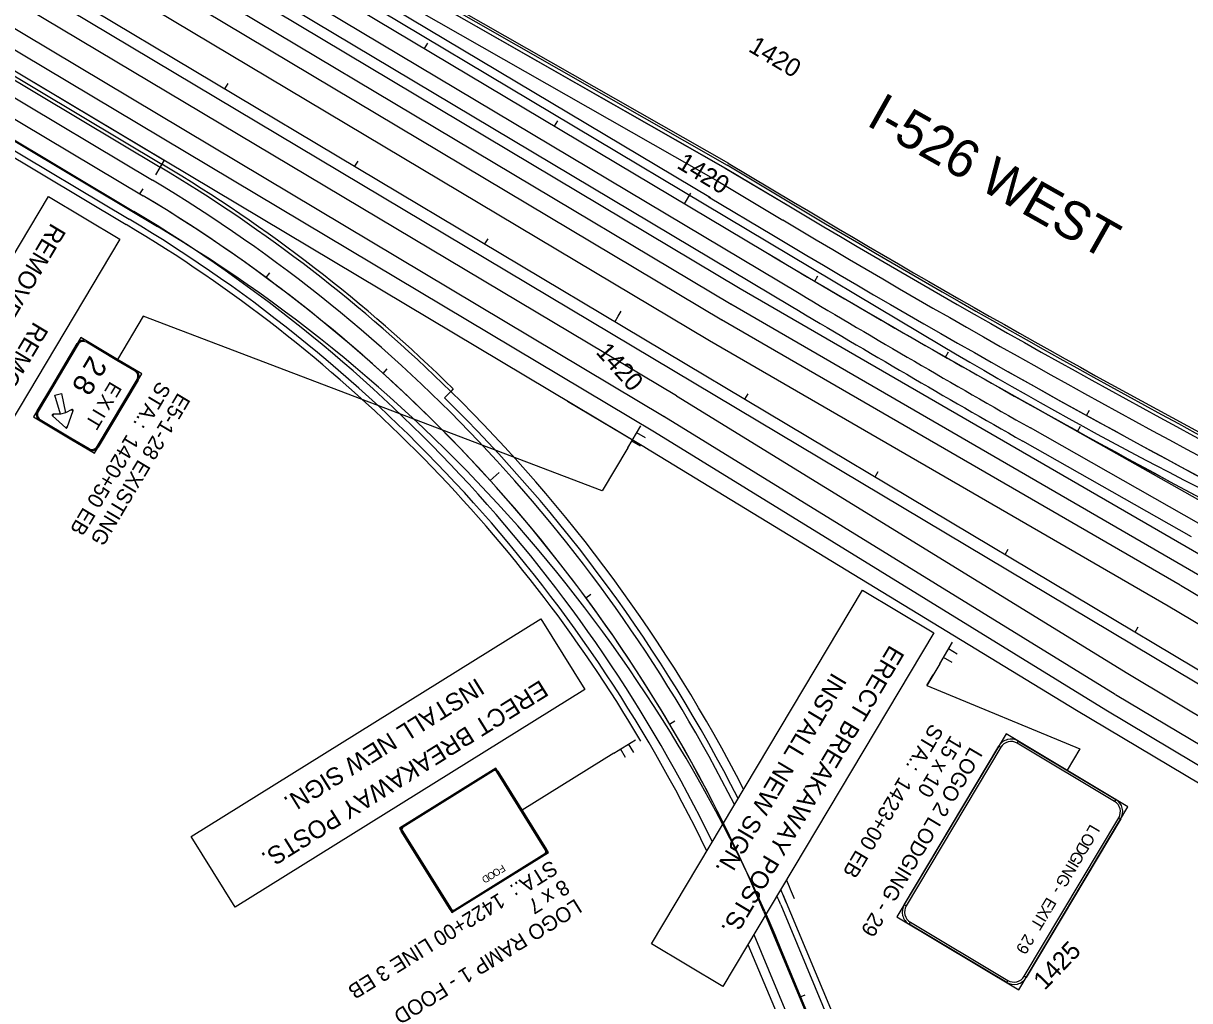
# Model space of a CAD drawing. Extents: x 2338610 to 2351914, y 366540 to 376484.
# Drawn here: x 2347857 to 2348627, y 368264 to 368909 of the extents above; entities that cross this region are included whole.
import ezdxf

# ---------------------------------------------------------------- set-up
doc = ezdxf.new("R2010")
doc.units = 0
for name, color, linetype in [('RD_HC_Cl', 7, 'Continuous'), ('RD_HC_CL_Rel', 7, 'Continuous'), ('RD_PD_Final_LnLine', 7, 'Continuous'), ('RD_PD_Final_TrvlWay', 7, 'Continuous'), ('RD_PD_GR', 7, 'Continuous'), ('RD_PD_MedBWall', 7, 'Continuous'), ('RD_PD_MedGR', 7, 'Continuous'), ('RD_PD_NOISE-WALL-GM', 7, 'Continuous'), ('RD_PD_PaveShd', 7, 'Continuous'), ('TR PM UNASSIGNED 3', 7, 'Continuous'), ('TR SN EXISTING - BREAK-AWAY SIGN SUPPORTS', 7, 'Continuous'), ('TR SN EXTRUDED PANEL SIGNS - GROUND MOUNTED', 7, 'Continuous'), ('TR SN EXTRUDED PANEL SIGNS- MOUNTED OVERHEAD', 7, 'Continuous'), ('TR SN UNASSIGNED 4', 7, 'Continuous'), ('TR SN UNASSIGNED 7', 7, 'Continuous')]:
    doc.layers.add(name, color=color, linetype=linetype)

msp = doc.modelspace()

# ---------------------------------------------------------------- linework, layer by layer
at = {"layer": 'RD_HC_Cl'}
for p, q in [((2346281.57, 369885.43), (2351112.4, 367003.22)), ((2346606.48, 369804.53), (2348463.13, 368696.8)), ((2346606.48, 369804.53), (2348463.13, 368696.8)), ((2346606.48, 369804.53), (2348463.13, 368696.8)), ((2346606.48, 369804.53), (2348463.13, 368696.8))]:
    msp.add_line(p, q, dxfattribs=at)
msp.add_arc((2349948.99, 371187.23), 2900, 239.17851, 245.9774, dxfattribs=at)
msp.add_arc((2349948.99, 371187.23), 2900, 239.17851, 245.9774, dxfattribs=at)
msp.add_arc((2349948.99, 371187.23), 2900, 239.17851, 245.9774, dxfattribs=at)
msp.add_arc((2349948.99, 371187.23), 2900, 239.17851, 245.9774, dxfattribs=at)
at = {"layer": 'RD_HC_CL_Rel'}
for p, q in [((2346236.27, 369809.5), (2347935.64, 368795.61)), ((2347900.51, 369024.72), (2348345.88, 368759)), ((2348500.93, 368669.16), (2349129.79, 368315.43)), ((2348345.74, 368322.92), (2348612.9, 367684.58))]:
    msp.add_line(p, q, dxfattribs=at)
for centre, radius, start, end in [((2347423.27, 367936.84), 1000, 22.71075, 59.17851), ((2351938.58, 374780.68), 7012, 239.178507, 240.642806), ((2351938.58, 374780.68), 7000, 240.642806, 245.882475), ((2348774.65, 368059.29), 214.01, 62.97341, 174.06692)]:
    msp.add_arc(centre, radius, start, end, dxfattribs=at)
at = {"layer": 'RD_PD_Final_LnLine'}
for p, q in [((2346262.53, 369853.51), (2348279.79, 368649.96)), ((2346236.27, 369809.5), (2347935.64, 368795.61)), ((2346236.75, 369794.56), (2347945.19, 368775.26)), ((2346236.75, 369794.56), (2347945.19, 368775.26)), ((2346236.75, 369794.56), (2347945.19, 368775.26)), ((2346236.75, 369794.56), (2347945.19, 368775.26)), ((2346978.67, 369512.8), (2348317.92, 368713.76)), ((2348310.4, 368794.14), (2347906.4, 369035.17)), ((2347900.51, 369024.72), (2348345.88, 368759)), ((2348309.13, 368794.89), (2348352.02, 368769.3)), ((2348317.78, 368713.85), (2348620.78, 368538.7)), ((2348279.7, 368650.01), (2348577.74, 368466.56)), ((2348620.92, 368538.62), (2349820.78, 367822.75)), ((2348577.88, 368466.48), (2349209.46, 368089.66)), ((2348346.67, 368320.69), (2348585.38, 367750.35)), ((2348611.02, 367683.86), (2348357, 368298.46)), ((2348611.02, 367683.86), (2348357, 368298.46)), ((2348611.02, 367683.86), (2348357, 368298.46)), ((2348611.02, 367683.86), (2348357, 368298.46))]:
    msp.add_line(p, q, dxfattribs=at)
for centre, radius, start, end in [((2347423.27, 367936.84), 1000, 26.39949, 59.17851), ((2347432.83, 367916.49), 1000, 22.45591, 59.17851), ((2347432.83, 367916.49), 1000, 22.45591, 59.17851), ((2347432.83, 367916.49), 1000, 22.45591, 59.17851), ((2347432.83, 367916.49), 1000, 22.45591, 59.17851), ((2351938.58, 374780.68), 7000, 239.178507, 245.882475), ((2351938.58, 374780.68), 7012, 239.178507, 242.089491), ((2351938.58, 374780.68), 7012, 240.642806, 243.703137)]:
    msp.add_arc(centre, radius, start, end, dxfattribs=at)
at = {"layer": 'RD_PD_Final_TrvlWay'}
for p, q in [((2346256.38, 369843.21), (2348273.55, 368639.71)), ((2346242.42, 369819.8), (2347941.79, 368805.92)), ((2346217.64, 369806.64), (2347929.49, 368785.3)), ((2346984.82, 369523.11), (2348324.07, 368724.07)), ((2347907.65, 369037.48), (2348315.23, 368805.23)), ((2347894.36, 369014.41), (2348368.91, 368731.28)), ((2348315.23, 368805.23), (2348358.17, 368779.61)), ((2348323.79, 368724.24), (2348626.93, 368549.01)), ((2349153.03, 368283.92), (2348521.76, 368642.31)), ((2348273.55, 368639.71), (2348571.59, 368456.26)), ((2348626.93, 368549.01), (2349813.16, 367841.27)), ((2348571.59, 368456.26), (2349076.83, 368154.82)), ((2348356.81, 368327.55), (2348396.32, 368233.15)), ((2348339.03, 368307.87), (2348438.16, 368071.02))]:
    msp.add_line(p, q, dxfattribs=at)
for centre, radius, start, end in [((2347423.27, 367936.84), 1012, 26.83591, 59.17851), ((2347423.27, 367936.84), 988, 25.95023, 59.17851), ((2351938.58, 374780.68), 6988, 239.178507, 245.882475), ((2352567.57, 375768.6), 8194.67, 239.178507, 240.415096), ((2347423.27, 367936.84), 1012, 22.71075, 23.075), ((2348774.64, 368059.31), 230, 61.0108, 285.1623), ((2348774.64, 368059.31), 214, 61.0108, 285.16043)]:
    msp.add_arc(centre, radius, start, end, dxfattribs=at)
at = {"layer": 'RD_PD_GR'}
msp.add_line((2347001.09, 369327.57), (2347924.37, 368776.72), dxfattribs=at)
for centre, radius, start, end in [((2347423.27, 367936.84), 978, 30.66777, 59.17851), ((2347423.27, 367936.84), 1022, 27.19021, 45.55608), ((2347423.27, 367936.84), 1022, 22.71075, 23.48282), ((2348774.64, 368059.31), 240, 81.15571, 162.94062)]:
    msp.add_arc(centre, radius, start, end, dxfattribs=at)
at = {"layer": 'RD_PD_MedBWall'}
for p, q in [((2346754.62, 369528.57), (2347948.1, 368816.51)), ((2346753.42, 369526.57), (2347946.91, 368814.5)), ((2347912.6, 369046.17), (2348320.37, 368813.81)), ((2347913.76, 369048.19), (2348321.53, 368815.83)), ((2347946.91, 368814.5), (2347948.1, 368816.51)), ((2348320.17, 368813.93), (2348363.3, 368788.2)), ((2348321.37, 368815.93), (2348364.49, 368790.2)), ((2348140.52, 368668.15), (2348138.89, 368666.49))]:
    msp.add_line(p, q, dxfattribs=at)
for centre, radius, start, end in [((2347423.27, 367936.84), 1022, 45.55608, 59.17851), ((2347423.27, 367936.84), 1024.33, 45.55608, 59.17851), ((2351938.58, 374780.68), 6978, 239.178507, 245.882475), ((2351938.58, 374780.68), 6975.67, 239.178507, 245.882475)]:
    msp.add_arc(centre, radius, start, end, dxfattribs=at)
at = {"layer": 'RD_PD_MedGR'}
msp.add_line((2347144.89, 369361.04), (2349123.23, 368180.7), dxfattribs=at)
at = {"layer": 'RD_PD_NOISE-WALL-GM'}
for p, q in [((2347913.76, 369048.19), (2348321.53, 368815.83)), ((2347914.5, 369049.5), (2348322.27, 368817.14)), ((2348322.13, 368817.22), (2348365.26, 368791.49))]:
    msp.add_line(p, q, dxfattribs=at)
msp.add_arc((2351938.58, 374780.68), 6974.17, 239.178507, 242.204196, dxfattribs=at)
at = {"layer": 'RD_PD_PaveShd'}
for p, q in [((2346247.54, 369828.39), (2347946.91, 368814.5)), ((2346250.23, 369832.9), (2347949.6, 368819.01)), ((2346250.23, 369832.9), (2348267.49, 368629.35)), ((2347129.05, 369404.45), (2348309.73, 368700.02)), ((2347107.36, 369368.09), (2348288.04, 368663.67)), ((2347117.12, 369263), (2347926.41, 368780.15)), ((2347580.76, 369181.52), (2348330.01, 368734.5)), ((2347912.6, 369046.17), (2348320.18, 368813.91)), ((2347889.23, 369005.82), (2348363.79, 368722.69)), ((2347949.6, 368819.01), (2347943.84, 368809.35)), ((2348320.36, 368813.81), (2348363.3, 368788.2)), ((2348330.01, 368734.5), (2348633, 368559.35)), ((2348309.77, 368700), (2348612.75, 368524.86)), ((2348134.69, 368662.2), (2348138.89, 368666.49)), ((2348216.02, 368660.06), (2348267.49, 368629.35)), ((2348288.09, 368663.64), (2348586.1, 368480.21)), ((2348267.03, 368629.63), (2348552.32, 368456.11)), ((2348628.23, 368570.36), (2348516.82, 368633.61)), ((2348612.75, 368524.86), (2349277.31, 368128.37)), ((2348586.11, 368480.2), (2349221.38, 368101.18)), ((2348552.32, 368456.11), (2348815.37, 368299.17)), ((2348358.28, 368334.4), (2348400.01, 368234.69)), ((2348335.2, 368301.47), (2348432.54, 368068.89))]:
    msp.add_line(p, q, dxfattribs=at)
for centre, radius, start, end in [((2351938.58, 374780.68), 6978, 239.178507, 245.882475), ((2347423.27, 367936.84), 982, 25.7206, 59.17851), ((2352567.57, 375768.6), 8204.67, 239.178507, 240.415096), ((2347423.27, 367936.84), 1016, 26.97863, 45.55608), ((2347423.27, 367936.84), 1016, 22.71075, 23.23935), ((2348774.64, 368059.31), 234, 81.2484, 268.00355)]:
    msp.add_arc(centre, radius, start, end, dxfattribs=at)
at = {"layer": 'TR SN EXISTING - BREAK-AWAY SIGN SUPPORTS'}
for points in [[(2347920.2, 368767.03), (2347780.86, 368533.48), (2347733.7, 368561.61), (2347873.04, 368795.17)], [(2348457.92, 368507.15), (2348318.58, 368273.6), (2348271.42, 368301.74), (2348410.76, 368535.29)], [(2348227.35, 368469.77), (2347996.52, 368325.96), (2347967.48, 368372.57), (2348198.31, 368516.38)]]:
    msp.add_lwpolyline(points, close=True, dxfattribs=at)
at = {"layer": 'TR SN EXTRUDED PANEL SIGNS - GROUND MOUNTED'}
for p, q in [((2348255.89, 368629.29), (2348264.44, 368643.63)), ((2348267.44, 368635.75), (2348261.71, 368639.17)), ((2348264.15, 368630.23), (2348258.44, 368633.63)), ((2348461.84, 368486.56), (2348470.39, 368500.89)), ((2348473.39, 368493.01), (2348467.66, 368496.43)), ((2348470.1, 368487.49), (2348464.39, 368490.9)), ((2348246.63, 368427.75), (2348260.8, 368436.57)), ((2348259.85, 368428.2), (2348256.33, 368433.86)), ((2348246.63, 368427.75), (2348185.99, 368389.97)), ((2348254.4, 368424.8), (2348250.89, 368430.44))]:
    msp.add_line(p, q, dxfattribs=at)
at = {"layer": 'TR SN EXTRUDED PANEL SIGNS- MOUNTED OVERHEAD'}
for p, q in [((2347935.71, 368716.15), (2347918.68, 368687.61)), ((2348238.86, 368600.75), (2347935.71, 368716.15)), ((2347894.51, 368702.03), (2347875.29, 368669.81)), ((2347892.11, 368698), (2347892.78, 368697.6)), ((2347918.68, 368687.61), (2347894.51, 368702.03)), ((2347894.51, 368702.03), (2347894.51, 368702.03)), ((2347894.51, 368702.03), (2347894.51, 368702.03)), ((2347898.14, 368698.95), (2347898.54, 368699.62)), ((2347934.79, 368678), (2347918.68, 368687.61)), ((2347918.68, 368687.61), (2347918.68, 368687.61)), ((2347918.68, 368687.61), (2347918.68, 368687.61)), ((2347930.76, 368680.4), (2347930.36, 368679.73)), ((2347903.55, 368625.64), (2347934.79, 368678)), ((2347931.71, 368674.37), (2347932.38, 368673.97)), ((2347875.29, 368669.81), (2347863.27, 368649.67)), ((2347875.29, 368669.81), (2347875.29, 368669.81)), ((2347875.29, 368669.81), (2347875.29, 368669.81)), ((2347863.27, 368649.67), (2347887.44, 368635.25)), ((2347866.35, 368653.29), (2347865.67, 368653.69)), ((2347875.82, 368650.31), (2347876.21, 368650.74)), ((2347876.21, 368650.74), (2347876.21, 368651.33)), ((2347888.63, 368654.47), (2347888.91, 368653.95)), ((2347888.91, 368653.95), (2347889.46, 368653.75)), ((2347867.3, 368647.26), (2347867.7, 368647.94)), ((2347884.95, 368642.87), (2347884.56, 368642.44)), ((2347885.51, 368642.68), (2347884.95, 368642.87)), ((2347887.44, 368635.25), (2347903.55, 368625.64)), ((2347899.92, 368628.71), (2347899.52, 368628.04)), ((2347905.95, 368629.66), (2347905.28, 368630.07)), ((2348255.89, 368629.29), (2348238.86, 368600.75)), ((2348461.84, 368486.56), (2348453.32, 368472.28)), ((2348453.32, 368472.28), (2348457.58, 368479.42)), ((2348453.32, 368472.28), (2348554.47, 368430.63)), ((2348512.93, 368434.24), (2348513.74, 368435.58)), ((2348500.87, 368432.33), (2348502.22, 368431.53)), ((2348554.47, 368430.63), (2348545.96, 368416.36)), ((2348166.64, 368416.59), (2348167.05, 368415.93)), ((2348169.2, 368415.43), (2348169.87, 368415.84)), ((2348578.18, 368397.13), (2348577.38, 368395.79)), ((2348580.08, 368385.07), (2348581.43, 368384.27)), ((2348106.17, 368376.16), (2348106.84, 368376.58)), ((2348107.34, 368378.73), (2348106.93, 368379.39)), ((2348202.11, 368364.09), (2348201.44, 368363.68)), ((2348200.94, 368361.53), (2348201.36, 368360.86)), ((2348439.74, 368326.81), (2348438.4, 368327.61)), ((2348139.08, 368324.83), (2348138.41, 368324.41)), ((2348141.64, 368323.66), (2348141.23, 368324.33)), ((2348441.65, 368314.75), (2348442.45, 368316.09)), ((2348518.95, 368279.55), (2348517.61, 368280.35)), ((2348506.89, 368277.65), (2348506.09, 368276.3))]:
    msp.add_line(p, q, dxfattribs=at)
for points in [[(2347892.78, 368697.6), (2347875.96, 368669.4), (2347875.29, 368669.81), (2347892.11, 368698), (2347892.78, 368697.6), (2347892.78, 368697.6)], [(2347918.28, 368686.94), (2347898.14, 368698.95), (2347898.54, 368699.62), (2347918.68, 368687.61), (2347918.28, 368686.94), (2347918.28, 368686.94)], [(2347930.36, 368679.73), (2347918.28, 368686.94), (2347918.68, 368687.61), (2347930.76, 368680.4), (2347930.36, 368679.73), (2347930.36, 368679.73)], [(2347905.28, 368630.07), (2347931.71, 368674.37), (2347932.38, 368673.97), (2347905.95, 368629.66), (2347905.28, 368630.07), (2347905.28, 368630.07)], [(2347875.96, 368669.4), (2347866.35, 368653.29), (2347865.67, 368653.69), (2347875.29, 368669.81), (2347875.96, 368669.4), (2347875.96, 368669.4)], [(2347877.22, 368663.9), (2347881.77, 368665.05), (2347884.41, 368652.21), (2347881, 368651.35), (2347877.22, 368663.9), (2347877.22, 368663.9)], [(2347884.95, 368642.87), (2347885.51, 368642.68), (2347889.46, 368653.75), (2347888.91, 368653.95), (2347888.63, 368654.47), (2347884.41, 368652.21), (2347881, 368651.35), (2347876.21, 368651.33), (2347876.21, 368650.74), (2347875.82, 368650.31), (2347884.56, 368642.44), (2347884.95, 368642.87), (2347884.95, 368642.87)], [(2347867.7, 368647.94), (2347887.84, 368635.92), (2347887.44, 368635.25), (2347867.3, 368647.26), (2347867.7, 368647.94), (2347867.7, 368647.94)], [(2347887.84, 368635.92), (2347899.92, 368628.71), (2347899.52, 368628.04), (2347887.44, 368635.25), (2347887.84, 368635.92), (2347887.84, 368635.92)], [(2348505.68, 368440.39), (2348433.59, 368319.56), (2348514.14, 368271.5), (2348586.23, 368392.33), (2348505.68, 368440.39), (2348505.68, 368440.39)], [(2348577.38, 368395.79), (2348512.93, 368434.24), (2348513.74, 368435.58), (2348578.18, 368397.13), (2348577.38, 368395.79), (2348577.38, 368395.79)], [(2348502.22, 368431.53), (2348439.74, 368326.81), (2348438.4, 368327.61), (2348500.87, 368432.33), (2348502.22, 368431.53), (2348502.22, 368431.53)], [(2348168.63, 368417.83), (2348104.93, 368378.15), (2348139.65, 368322.42), (2348203.35, 368362.1), (2348168.63, 368417.83), (2348168.63, 368417.83)], [(2348167.05, 368415.93), (2348107.34, 368378.73), (2348106.93, 368379.39), (2348166.64, 368416.59), (2348167.05, 368415.93), (2348167.05, 368415.93)], [(2348201.44, 368363.68), (2348169.2, 368415.43), (2348169.87, 368415.84), (2348202.11, 368364.09), (2348201.44, 368363.68), (2348201.44, 368363.68)], [(2348517.61, 368280.35), (2348580.08, 368385.07), (2348581.43, 368384.27), (2348518.95, 368279.55), (2348517.61, 368280.35), (2348517.61, 368280.35)], [(2348106.84, 368376.58), (2348139.08, 368324.83), (2348138.41, 368324.41), (2348106.17, 368376.16), (2348106.84, 368376.58), (2348106.84, 368376.58)], [(2348141.23, 368324.33), (2348200.94, 368361.53), (2348201.36, 368360.86), (2348141.64, 368323.66), (2348141.23, 368324.33), (2348141.23, 368324.33)], [(2348442.45, 368316.09), (2348506.89, 368277.65), (2348506.09, 368276.3), (2348441.65, 368314.75), (2348442.45, 368316.09), (2348442.45, 368316.09)]]:
    msp.add_lwpolyline(points, close=True, dxfattribs=at)
for centre, radius, start, end in [((2347896.14, 368695.6), 4.69, 59.17836, 149.17857), ((2347896.14, 368695.6), 3.91, 59.17836, 149.17857), ((2347928.36, 368676.37), 4.69, 329.17872, 59.17836), ((2347928.36, 368676.37), 3.91, 329.17872, 59.17836), ((2347869.7, 368651.29), 4.69, 149.17857, 239.17878), ((2347869.7, 368651.29), 3.91, 149.17857, 239.17878), ((2347876.21, 368650.74), 0.586, 90.21662, 228.00037), ((2347888.91, 368653.95), 0.586, 340.35655, 118.14087), ((2347884.95, 368642.87), 0.586, 228.00037, 340.35625), ((2347901.92, 368632.07), 4.69, 239.17851, 329.17872), ((2347901.92, 368632.07), 3.91, 239.17851, 329.17872), ((2348508.93, 368427.52), 9.38, 59.17836, 149.17857), ((2348508.93, 368427.52), 7.82, 59.17836, 149.17857), ((2348167.88, 368414.6), 2.35, 31.92286, 121.92307), ((2348167.88, 368414.6), 1.56, 31.92286, 121.92307), ((2348573.37, 368389.08), 7.82, 329.17872, 59.17836), ((2348573.37, 368389.08), 9.38, 329.17872, 59.17836), ((2348108.17, 368377.4), 2.35, 121.92307, 211.92328), ((2348108.17, 368377.4), 1.56, 121.92307, 211.92328), ((2348200.12, 368362.85), 2.35, 301.92323, 31.92286), ((2348200.12, 368362.85), 1.56, 301.92323, 31.92286), ((2348446.45, 368322.81), 9.38, 149.17857, 239.17878), ((2348446.45, 368322.81), 7.82, 149.17857, 239.17878), ((2348140.4, 368325.65), 2.35, 211.92301, 301.92323), ((2348140.4, 368325.65), 1.56, 211.92301, 301.92323), ((2348510.89, 368284.36), 9.38, 239.17851, 329.17872), ((2348510.89, 368284.36), 7.82, 239.17851, 329.17872)]:
    msp.add_arc(centre, radius, start, end, dxfattribs=at)
at = {"layer": 'TR SN UNASSIGNED 7'}
for p, q in [((2348121.57, 368892.82), (2348123.62, 368896.26)), ((2347989.73, 368866.3), (2347991.78, 368869.73)), ((2348207.45, 368841.59), (2348209.5, 368845.02)), ((2348075.6, 368815.06), (2348077.65, 368818.49)), ((2347933.58, 368796.84), (2347935.63, 368800.27)), ((2348293.33, 368790.35), (2348297.42, 368797.22)), ((2348161.48, 368763.82), (2348163.53, 368767.26)), ((2348016.89, 368741.59), (2348019.26, 368744.81)), ((2348379.26, 368739.21), (2348381.29, 368742.65)), ((2348249.41, 368716.02), (2348251.46, 368719.46)), ((2348247.36, 368712.59), (2348249.41, 368716.02)), ((2348465.77, 368689.06), (2348467.76, 368692.54)), ((2348094.26, 368678.31), (2348096.95, 368681.27)), ((2348333.23, 368661.35), (2348335.28, 368664.79)), ((2348558.88, 368650.62), (2348560.81, 368654.12)), ((2348552.88, 368639.94), (2348554.84, 368643.42)), ((2348164.93, 368607.62), (2348170.87, 368612.98)), ((2348419.11, 368610.11), (2348421.16, 368613.55)), ((2348504.99, 368558.88), (2348507.04, 368562.31)), ((2348228.19, 368530.22), (2348231.41, 368532.6)), ((2348590.86, 368507.64), (2348592.91, 368511.08)), ((2348283.41, 368446.9), (2348286.85, 368448.94)), ((2348369.34, 368266.54), (2348373.03, 368268.08))]:
    msp.add_line(p, q, dxfattribs=at)

# ---------------------------------------------------------------- texts
at = {"layer": 'TR PM UNASSIGNED 3'}
for s, rotation, p in [('STA.:  1420+50 EB', 239.17851, (2347945.87, 368673.82)), ('E5-1-28 EXISTING', 239.17851, (2347958.75, 368666.13)), ('STA.:  1423+00 EB', 239.22937, (2348456.25, 368447.76)), ('15 x 10', 239.22937, (2348469.14, 368440.09)), ('LOGO 2 LODGING - 29', 239.22937, (2348482.03, 368432.41)), ('STA.:  1422+00 LINE 3 EB', 211.92301, (2348205.36, 368357.42)), ('8 x 7', 211.92301, (2348213.29, 368344.69)), ('LOGO RAMP 1 - FOOD', 211.92301, (2348221.22, 368331.96))]:
    msp.add_text(s, height=10, rotation=rotation, dxfattribs=at).set_placement(p)
at = {"layer": 'TR SN EXISTING - BREAK-AWAY SIGN SUPPORTS'}
for s, rotation, p in [('REMOVE BREAKAWAY POSTS.', 239.17859, (2347875.12, 368778.2)), ('REMOVE SIGN.', 239.17859, (2347863.54, 368713.05)), ('ERECT BREAKAWAY POSTS.', 239.17859, (2348429, 368499.68)), ('INSTALL NEW SIGN.', 239.17859, (2348390.91, 368481.59)), ('ERECT BREAKAWAY POSTS.', 211.9231, (2348198.21, 368476.36)), ('INSTALL NEW SIGN.', 211.9231, (2348156.07, 368477.72))]:
    msp.add_text(s, height=11.7187, rotation=rotation, dxfattribs=at).set_placement(p)
at = {"layer": 'TR SN EXTRUDED PANEL SIGNS- MOUNTED OVERHEAD'}
for s, height, rotation, p in [('2', 14.07, 239.17851, (2347900.58, 368690.85)), ('8', 14.07, 239.17851, (2347893.35, 368678.73)), ('E', 9.38, 239.17851, (2347913.98, 368673.63)), ('X', 9.38, 239.17851, (2347908.96, 368665.23)), ('T', 9.38, 239.17851, (2347901.04, 368651.94)), ('I', 9.38, 239.17851, (2347903.35, 368655.81)), ('L', 7.82, 239.17851, (2348561.41, 368381.24)), ('O', 7.82, 239.17851, (2348558.22, 368375.89)), ('D', 7.82, 239.17851, (2348554.47, 368369.59)), ('I', 7.82, 239.17851, (2348547.39, 368357.74)), ('G', 7.82, 239.17851, (2348551.02, 368363.83)), ('O', 4.69, 211.92301, (2348166.38, 368350.13)), ('O', 4.69, 211.92301, (2348169.93, 368352.34)), ('F', 4.69, 211.92301, (2348173.1, 368354.31)), ('N', 7.82, 239.17851, (2348545.83, 368355.12)), ('D', 4.69, 211.92301, (2348162.65, 368347.8)), ('G', 7.82, 239.17851, (2348542.2, 368349.04)), ('-', 7.82, 239.17851, (2348537.11, 368340.5)), ('X', 7.82, 239.17851, (2348529.51, 368327.76)), ('E', 7.82, 239.17851, (2348532.7, 368333.11)), ('I', 7.82, 239.17851, (2348526.07, 368322)), ('T', 7.82, 239.17851, (2348524.69, 368319.69)), ('2', 7.82, 239.17851, (2348518.25, 368308.88)), ('9', 7.82, 239.17851, (2348514.8, 368303.12))]:
    msp.add_text(s, height=height, rotation=rotation, dxfattribs=at).set_placement(p)
at = {"layer": 'TR SN UNASSIGNED 4'}
msp.add_text('I-526 WEST', height=25, rotation=330.50912, dxfattribs=at).set_placement((2348412.58, 368842.65))
at = {"layer": 'TR SN UNASSIGNED 7'}
for s, rotation, p in [('1420', 329.17851, (2348334.81, 368891.36)), ('1420', 329.17851, (2348287.52, 368814.39)), ('1420', 312.12693, (2348234.21, 368692.03)), ('1425', 46.16536, (2348531.21, 368270.68))]:
    msp.add_text(s, height=12, rotation=rotation, dxfattribs=at).set_placement(p)

doc.saveas('drawing.dxf')
